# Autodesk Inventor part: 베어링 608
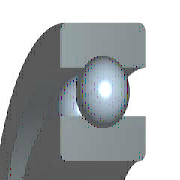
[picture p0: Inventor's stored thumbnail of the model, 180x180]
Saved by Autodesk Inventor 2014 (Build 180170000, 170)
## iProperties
IsCustomPart: 1
Company: 한국ATC센터
Created: 2014-07
Part Number: 베어링 608
Material: 강, 연강
Description: 깊은 그루브 볼 베어링
Document SubType Name: Modeling
Standard: KS B 2023
Designer: KYOUNG IL JANG
Standards Organization: KS
Language: ko-KR
Size Designation: 608 - 8 x 22 x 7
Categories: <MemberInstance><Categories><Category DisplayName="샤프트 부품" InternalName="7f7aeb1f-a693-4053-b835-cee3144e0d98" Mnemonic="SHFT"><Category DisplayName="베어링" Inter
Density: 1 g/cm^3
Appearance: 강철
Author: KYOUNG IL JANG
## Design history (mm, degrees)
sketch "스케치" dims "d0" = 3.64 (= -0.26 x WD + 0.26 x BD)
  geometry: L1 (1.68, 7.5)-(5.32, 7.5); L2 (3.5, 7.5)-(3.5, 5.68); L3 (3.5, 7.5)-(3.5, 9.32); L4 (2.148, 6.282)-(0, 6.282); L5 (0, 4)-(7, 4); L6 (2.148, 8.718)-(0, 8.718); L7 (0, 11)-(7, 11); L8 (7, 4)-(7, 6.282); L9 (4.852, 6.282)-(7, 6.282); L10 (4.852, 8.718)-(7, 8.718); L11 (7, 11)-(7, 8.718); L12 (-1.4, 0)-(8.4, 0) reference; L13 (0, -0.3)-(0, 5.3) reference
  constraints: 22 end point, 4 point on line, 2 collinear, 2 perpendicular, 2 symmetric about line, 1 midpoint, 1 parallel, 14 other
  dimensions: "d9" = 8 diameter of L5 L12 (= WD); "d11" = 22 diameter of L7 L12 (= BD); "d12" = 7 distance between parallel lines of L8 L13 (= KB); "d13" = 12.564 diameter of L9 L12 (= 0.326 x BD + 0.674 x WD)
revolve "본체" stored, may be unused: angle "d6" = 90 deg
revolve "볼" stored, may be unused: angle "d7" = 90 deg
pattern_circular "IDS_ARRAYBALL[SIMPL:T]" dims angle "d3" = 360 deg
body "Solid1"
fillet "모깎기1" dims "d1" = 0.3 (= KRS)
other parameters: "WD" = 8 [user parameter; used in 5 equation terms], "BD" = 22 [user parameter; used in 5 equation terms], "KB" = 7 [user parameter; used in 1 equation term], "KRS" = 0.3 [user parameter; used in 1 equation term], "d4" = 0, "d5" = 0, "d8" = 0, "d14" = 0, "d15" = 0, "BBA" = 0 [user parameter], "BC0" = 1370000 [user parameter], "BC" = 3250000 [user parameter], "BR" = 11 (= 0.5 x BD) [user parameter], "WR" = 4 (= 0.5 x WD) [user parameter]
